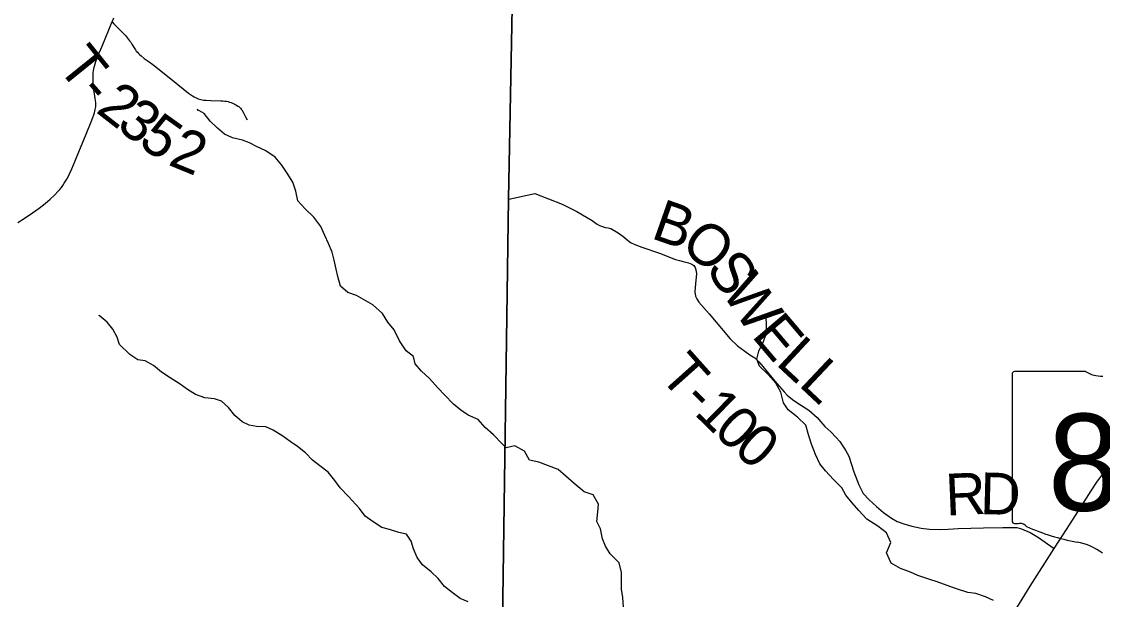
# Model space of a CAD drawing. Extents: x 0 to 34, y 0 to 22.
# Drawn here: x 4.145 to 5.615, y 19 to 19.787 of the extents above; entities that cross this region are included whole.
import ezdxf

# ---------------------------------------------------------------- set-up
doc = ezdxf.new("R2010")
doc.units = 0
for name, color, linetype in [('GM_X_Corporation', 7, 'Continuous'), ('GM_X_Minor_River', 7, 'Continuous'), ('GM_X_State_Location', 7, 'Continuous'), ('GM_X_State_Route', 7, 'Continuous'), ('GM_X_State_Shield', 7, 'Continuous'), ('GM_X_Township_Road', 7, 'Continuous'), ('GM_X_Township_Road_Text', 7, 'Continuous')]:
    doc.layers.add(name, color=color, linetype=linetype)

msp = doc.modelspace()

# ---------------------------------------------------------------- linework, layer by layer
at = {"layer": 'GM_X_Corporation'}
for points in [[(4.7823, 18.128), (4.7905, 18.3604), (4.8074, 19.5455), (4.8169, 20.042), (4.8194, 20.1261), (5.11, 20.116), (6.0551, 20.0845), (6.4901, 20.0752), (6.7204, 20.0659), (7.3691, 20.0515), (7.3901, 20.051), (7.814, 20.0425), (8.4311, 20.028), (8.4311, 21.3734), (1.6311, 21.3734)], [(4.0508, 18.1454), (4.7823, 18.128), (4.7905, 18.3604), (4.8074, 19.5455), (4.8169, 20.042), (4.8194, 20.1261), (5.11, 20.116), (6.0551, 20.0845), (6.4901, 20.0752), (6.7204, 20.0659), (7.3691, 20.0515), (7.3901, 20.051), (7.814, 20.0425), (8.4311, 20.028), (8.4311, 21.3734), (2.7987, 21.3734)], [(8.4311, 14.5734), (8.4311, 20.028), (7.814, 20.0425), (7.3901, 20.051), (7.3691, 20.0515), (6.7204, 20.0659), (6.4901, 20.0752), (6.0551, 20.0845), (5.11, 20.116), (4.8194, 20.1261), (4.8169, 20.042), (4.8074, 19.5455), (4.7905, 18.3604), (4.7823, 18.128)], [(8.4311, 16.0029), (8.4311, 20.028), (7.814, 20.0425), (7.3901, 20.051), (7.3691, 20.0515), (6.7204, 20.0659), (6.4901, 20.0752), (6.0551, 20.0845), (5.11, 20.116), (4.8194, 20.1261), (4.8169, 20.042), (4.8074, 19.5455), (4.7905, 18.3604), (4.7823, 18.128)]]:
    msp.add_lwpolyline(points, dxfattribs=at)
at = {"layer": 'GM_X_Minor_River'}
for points in [[(4.798, 19.2123), (4.7868, 19.2243), (4.7754, 19.234), (4.7658, 19.2449), (4.7522, 19.2508), (4.7423, 19.2579), (4.7324, 19.2658), (4.7202, 19.2785), (4.711, 19.2883), (4.6999, 19.3007), (4.6889, 19.3108), (4.6805, 19.3209), (4.6781, 19.3308), (4.6679, 19.3386), (4.6591, 19.3522), (4.6517, 19.3669), (4.6433, 19.3774), (4.636, 19.3894), (4.6227, 19.401), (4.6007, 19.4137), (4.5889, 19.4177), (4.5786, 19.4267), (4.5751, 19.4396), (4.5728, 19.4494), (4.57, 19.4619), (4.5673, 19.4728), (4.5626, 19.4845), (4.5576, 19.4954), (4.5519, 19.5079), (4.5427, 19.5203), (4.5305, 19.5319), (4.5206, 19.5428), (4.5182, 19.5556), (4.5139, 19.5681), (4.5062, 19.5801), (4.499, 19.5914), (4.4898, 19.6019), (4.4772, 19.6105), (4.4647, 19.6165), (4.4548, 19.6217), (4.4454, 19.625), (4.4317, 19.6282), (4.4211, 19.6334), (4.4116, 19.6417), (4.4013, 19.651), (4.3933, 19.6615), (4.3838, 19.6668), (4.3849, 19.6656)], [(4.7525, 18.997), (4.7415, 19.0014), (4.7305, 19.0097), (4.7202, 19.0175), (4.7114, 19.0284), (4.7019, 19.0378), (4.6901, 19.0471), (4.6832, 19.0573), (4.6781, 19.069), (4.6747, 19.0792), (4.6685, 19.089), (4.6579, 19.0911), (4.6454, 19.0952), (4.6348, 19.0981), (4.6234, 19.1055), (4.6124, 19.1134), (4.6047, 19.1239), (4.5898, 19.14), (4.5784, 19.152), (4.5711, 19.1622), (4.5619, 19.1735), (4.5505, 19.182), (4.5406, 19.1895), (4.5311, 19.1997), (4.5201, 19.2083), (4.5102, 19.215), (4.5003, 19.2221), (4.487, 19.2306), (4.4771, 19.2351), (4.4646, 19.2353), (4.4544, 19.2371), (4.4449, 19.2419), (4.435, 19.2505), (4.4266, 19.2614), (4.4171, 19.2701), (4.4076, 19.273), (4.3944, 19.2744), (4.3815, 19.2792), (4.3708, 19.2859), (4.3609, 19.293), (4.3472, 19.3015), (4.3351, 19.3094), (4.3244, 19.3183), (4.313, 19.325), (4.3032, 19.3264), (4.2922, 19.3335), (4.2781, 19.347), (4.2749, 19.3572), (4.2692, 19.3678), (4.2612, 19.3775), (4.2505, 19.3865), (4.2505, 19.3869)], [(5.4668, 18.9987), (5.4559, 19.0036), (5.4427, 19.0082), (5.4321, 19.0097), (5.4166, 19.0143), (5.4037, 19.0192), (5.3905, 19.0242), (5.3803, 19.0272), (5.3641, 19.0325), (5.3539, 19.0371), (5.3406, 19.042), (5.3278, 19.0496), (5.3214, 19.0637), (5.3271, 19.0777), (5.3214, 19.0906), (5.3094, 19.0997), (5.2946, 19.1092), (5.2837, 19.1213), (5.2746, 19.1316), (5.2663, 19.1418), (5.2607, 19.1521), (5.2493, 19.1634), (5.2384, 19.1752), (5.2309, 19.1847), (5.2248, 19.1972), (5.2192, 19.2116), (5.2158, 19.2226), (5.2117, 19.2374), (5.2004, 19.2484), (5.1875, 19.2583), (5.1815, 19.2678), (5.1777, 19.2822), (5.1709, 19.2943), (5.1604, 19.3061), (5.1487, 19.3175), (5.1449, 19.3269), (5.1476, 19.3379), (5.154, 19.3512), (5.1578, 19.3618), (5.1582, 19.3724), (5.1579, 19.3857)], [(4.9639, 18.9895), (4.9628, 19.0027), (4.9609, 19.0141), (4.961, 19.0368), (4.9576, 19.0497), (4.9455, 19.0623), (4.9391, 19.0725), (4.935, 19.0824), (4.9323, 19.096), (4.9274, 19.1062), (4.9286, 19.1195), (4.9298, 19.1297), (4.9226, 19.1426), (4.9101, 19.1464), (4.8965, 19.1578), (4.8852, 19.1677), (4.875, 19.1768), (4.8618, 19.1818), (4.8486, 19.1871), (4.8357, 19.1898), (4.8289, 19.2019), (4.8157, 19.2091), (4.804, 19.2065), (4.798, 19.2123)]]:
    msp.add_lwpolyline(points, dxfattribs=at)
at = {"layer": 'GM_X_State_Route'}
msp.add_lwpolyline([(5.3703, 18.763), (5.3726, 18.7705), (5.3794, 18.7939), (5.3858, 18.8135), (5.39, 18.8262), (5.3957, 18.8398), (5.4045, 18.8555), (5.4181, 18.8758), (5.4335, 18.8972), (5.4689, 18.9449), (5.495, 18.9828), (5.517, 19.0181), (5.5496, 19.0692), (5.5613, 19.0877), (5.5751, 19.1092), (5.5997, 19.148), (5.6076, 19.1596), (5.6113, 19.1649), (5.6154, 19.1703)], dxfattribs=at)
at = {"layer": 'GM_X_State_Shield'}
for p, q in [((5.4924, 19.3069), (5.4924, 19.1068)), ((5.5921, 19.3103), (5.4956, 19.3103))]:
    msp.add_line(p, q, dxfattribs=at)
for centre, major_axis, start_param, end_param in [((5.4961, 19.3073), (0.00382, 0), 1.712693, 3.28349), ((5.6151, 19.3336), (0.037, 0), 4.042523, 4.731795), ((5.4962, 19.1063), (0.00385, 0), 3.00124, 4.508301), ((5.4968, 19.1268), (0.0294, 0), 4.665946, 4.897461), ((5.5028, 19.0952), (0.0106, 0), 0.519207, 1.627899), ((5.6366, 19.275), (0.2524, 0), 4.195997, 4.488961), ((5.5613, 19.0169), (0.079, 0), 0.823519, 1.323587)]:
    msp.add_ellipse(centre, major_axis=major_axis, ratio=0.8, start_param=start_param, end_param=end_param, dxfattribs=at)
at = {"layer": 'GM_X_Township_Road'}
msp.add_line((4.2683, 19.7861), (4.2706, 19.7915), dxfattribs=at)
for points in [[(4.1401, 19.5133), (4.1484, 19.5185), (4.1597, 19.5261), (4.1687, 19.5325), (4.177, 19.5389), (4.1841, 19.5448), (4.1899, 19.5504), (4.1949, 19.5558), (4.197, 19.5582), (4.1992, 19.561), (4.201, 19.5637), (4.203, 19.5666), (4.2046, 19.5692), (4.2065, 19.5723), (4.2082, 19.5754), (4.2101, 19.5794), (4.2132, 19.5861), (4.2177, 19.5969), (4.2229, 19.6095), (4.2251, 19.6146), (4.233, 19.6333), (4.2396, 19.65), (4.2418, 19.656), (4.2431, 19.6596), (4.2441, 19.6625), (4.2448, 19.6649), (4.2452, 19.6669), (4.2456, 19.6688), (4.2458, 19.6705), (4.2459, 19.6725), (4.2459, 19.6744), (4.2458, 19.6766), (4.2456, 19.6793), (4.2453, 19.682), (4.2433, 19.6942), (4.2425, 19.7022), (4.2422, 19.7085), (4.2422, 19.7112), (4.2422, 19.714), (4.2425, 19.7168), (4.2429, 19.7197), (4.2434, 19.7227), (4.2442, 19.7259), (4.2451, 19.7293), (4.2461, 19.7325), (4.2473, 19.736), (4.2489, 19.7402), (4.2546, 19.7533), (4.2598, 19.7652), (4.2638, 19.7756), (4.2666, 19.7822), (4.2683, 19.7861)], [(4.2683, 19.7861), (4.2707, 19.7836), (4.2749, 19.7792), (4.2814, 19.7728), (4.2863, 19.7675), (4.2891, 19.7641), (4.292, 19.7604), (4.2934, 19.7586), (4.2951, 19.7559), (4.2989, 19.7495), (4.2998, 19.7481), (4.301, 19.7465), (4.3025, 19.7448), (4.3039, 19.7432), (4.3055, 19.7417), (4.3075, 19.7399), (4.3119, 19.7364), (4.3186, 19.7319), (4.3237, 19.7283), (4.3367, 19.7178), (4.3574, 19.701), (4.372, 19.6894), (4.3759, 19.6865), (4.3774, 19.6854), (4.3796, 19.6842), (4.3835, 19.6823), (4.3852, 19.6816), (4.387, 19.681), (4.3906, 19.6802), (4.393, 19.6798), (4.3956, 19.6795), (4.4024, 19.6792), (4.416, 19.6789), (4.4188, 19.6788), (4.4216, 19.6785), (4.4235, 19.6782), (4.4258, 19.6777), (4.4279, 19.6771), (4.43, 19.6764), (4.432, 19.6756), (4.434, 19.6747), (4.4357, 19.6739), (4.4373, 19.673), (4.4392, 19.6717), (4.4403, 19.6709), (4.4426, 19.6688), (4.4437, 19.6676), (4.4446, 19.6664), (4.4465, 19.6633), (4.4501, 19.6561), (4.4517, 19.6528)], [(4.8076, 19.545), (4.8433, 19.5526), (4.8801, 19.5379), (4.9, 19.5282), (4.9211, 19.516), (4.9247, 19.5133), (4.9278, 19.5107), (4.931, 19.5089), (4.9349, 19.5075), (4.9388, 19.5065), (4.9428, 19.5059), (4.9464, 19.5049), (4.9566, 19.499), (4.9627, 19.4946), (4.9682, 19.49), (4.9715, 19.4873)], [(4.9715, 19.4873), (4.9731, 19.486), (4.9791, 19.483), (4.9885, 19.4797), (5.0127, 19.4714), (5.0343, 19.4629), (5.0397, 19.4615), (5.0448, 19.4602), (5.0519, 19.4583), (5.0545, 19.4575), (5.0568, 19.4562), (5.0594, 19.4544), (5.0611, 19.452), (5.0622, 19.4488), (5.0631, 19.4436), (5.0624, 19.4387), (5.0614, 19.4299), (5.0607, 19.4188), (5.0616, 19.4129), (5.0633, 19.4094), (5.0662, 19.4046), (5.0802, 19.3889), (5.1087, 19.355), (5.1187, 19.3454), (5.1285, 19.3378), (5.1355, 19.3331), (5.1422, 19.3288), (5.1478, 19.3235), (5.1533, 19.3172), (5.1695, 19.2973), (5.1822, 19.2827), (5.1865, 19.2779), (5.1936, 19.2723), (5.1994, 19.2681), (5.2059, 19.264), (5.2158, 19.2579), (5.2269, 19.2476), (5.2321, 19.2418), (5.2376, 19.2356), (5.2455, 19.2283), (5.2531, 19.2205), (5.2577, 19.2151), (5.2612, 19.2099), (5.2658, 19.2033), (5.2702, 19.1949), (5.277, 19.1739), (5.2837, 19.1563), (5.2898, 19.1444), (5.2978, 19.1355), (5.3078, 19.1265), (5.3175, 19.1184), (5.328, 19.1109), (5.3361, 19.106), (5.345, 19.1028), (5.356, 19.0998), (5.3687, 19.0969), (5.3798, 19.0956), (5.3941, 19.0953), (5.4051, 19.0959), (5.4188, 19.0965), (5.4535, 19.0974), (5.4796, 19.0981), (5.4888, 19.0982), (5.4988, 19.0978), (5.5051, 19.0964), (5.517, 19.0912), (5.5283, 19.0844), (5.5496, 19.0692)]]:
    msp.add_lwpolyline(points, dxfattribs=at)

# ---------------------------------------------------------------- texts
at = {"layer": 'GM_X_State_Location'}
msp.add_text('821', height=0.000189, rotation=0, dxfattribs=at).set_placement((5.5866, 19.1797))
at = {"layer": 'GM_X_State_Shield'}
msp.add_text('821', height=0.13184, dxfattribs=at).set_placement((5.5409, 19.1209))
at = {"layer": 'GM_X_Township_Road_Text'}
for s, rotation, p in [('T', 308.882, (4.1923, 19.7249)), ('-', 311.2178, (4.2206, 19.6899)), ('2', 322.1268, (4.2445, 19.6643)), ('3', 321.8717, (4.2721, 19.6428)), ('5', 324.342, (4.3018, 19.6196)), ('2', 337.6683, (4.3428, 19.5922)), ('B', 340.6591, (4.9996, 19.4923)), ('O', 320.2103, (5.039, 19.4795)), ('S', 303.839, (5.0746, 19.4506)), ('W', 303.9521, (5.096, 19.4187)), ('E', 310.1964, (5.1368, 19.3587)), ('L', 317.127, (5.1694, 19.3208)), ('T', 311.7435, (5.0107, 19.304)), ('L', 316.7397, (5.2005, 19.292)), ('-', 315.4195, (5.0417, 19.2694)), ('1', 315.6517, (5.0585, 19.2529)), ('0', 316.6176, (5.0843, 19.2277)), ('0', 318.6466, (5.1114, 19.2022)), ('R', 2.4792, (5.4027, 19.1142)), ('D', 358.5464, (5.4483, 19.1163))]:
    msp.add_text(s, height=0.0568, rotation=rotation, dxfattribs=at).set_placement(p)

doc.saveas('drawing.dxf')
